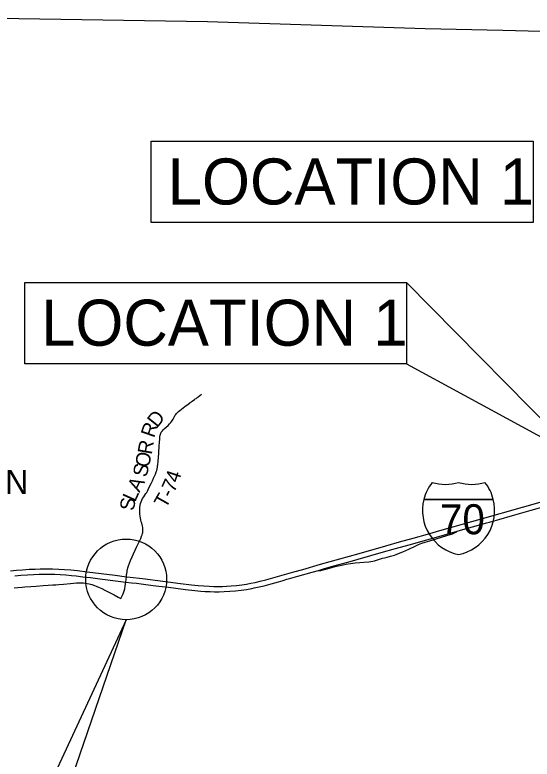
# Model space of a CAD drawing. Extents: x -29.6 to 34, y 0 to 22.
# Drawn here: x -16.109 to -14.201, y 3.352 to 6.1 of the extents above; entities that cross this region are included whole.
import ezdxf

# ---------------------------------------------------------------- set-up
doc = ezdxf.new("R2010")
doc.units = 0
for name, color, linetype in [('BR_P_Gen_Text', 7, 'Continuous'), ('Default', 7, 'Continuous'), ('GM_X_Corporation_Text', 7, 'Continuous'), ('GM_X_County_Road', 7, 'Continuous'), ('GM_X_Interchange_Ramps', 7, 'Continuous'), ('GM_X_Interstate_Route', 7, 'Continuous'), ('GM_X_Interstate_Shield', 7, 'Continuous'), ('GM_X_Township', 7, 'Continuous'), ('GM_X_Township_Road', 7, 'Continuous'), ('GM_X_Township_Road_Text', 7, 'Continuous'), ('GM_X_US_Route', 7, 'Continuous')]:
    doc.layers.add(name, color=color, linetype=linetype)

msp = doc.modelspace()

# ---------------------------------------------------------------- linework, layer by layer
at = {"layer": 'BR_P_Gen_Text'}
for points in [[(-15.6064, 5.6331), (-14.1976, 5.6331), (-14.1976, 5.3329), (-15.6064, 5.3329)], [(-16.0733, 5.1118), (-14.6646, 5.1118), (-14.6646, 4.8115), (-16.0733, 4.8115)], [(-14.6646, 5.1118), (-14.6646, 4.8115), (-14.027, 4.4641)], [(-16.0951, 3.013), (-16.0951, 2.7127), (-15.6989, 3.8667)]]:
    msp.add_lwpolyline(points, close=True, dxfattribs=at)
at = {"layer": 'Default'}
msp.add_circle((-15.6989, 4.0157), 0.149, dxfattribs=at)
at = {"layer": 'GM_X_County_Road'}
msp.add_lwpolyline([(-16.1119, 3.9847), (-16.0991, 3.9857), (-16.0829, 3.987), (-16.0724, 3.9879), (-16.0504, 3.9896), (-16.0313, 3.9909), (-16.0046, 3.9926), (-15.9861, 3.9941), (-15.9692, 3.9953), (-15.9582, 3.9961), (-15.9478, 3.9969), (-15.9304, 3.9984), (-15.9049, 4.0005), (-15.8817, 4.0025), (-15.8724, 4.0031), (-15.8648, 4.0031), (-15.856, 4.0026), (-15.8484, 4.0017), (-15.8432, 4.0009), (-15.8358, 3.9992), (-15.8251, 3.9963), (-15.8161, 3.9936), (-15.809, 3.991), (-15.8009, 3.9876), (-15.7893, 3.982), (-15.7773, 3.9761), (-15.7551, 3.9646), (-15.7433, 3.9583), (-15.7284, 3.9504), (-15.718, 3.9454)], dxfattribs=at)
at = {"layer": 'GM_X_Interchange_Ramps'}
msp.add_lwpolyline([(-14.9893, 4.0489), (-14.9877, 4.0487), (-14.986, 4.0486), (-14.9845, 4.0487), (-14.9827, 4.0488), (-14.9806, 4.0491), (-14.9766, 4.0499), (-14.958, 4.0547), (-14.9226, 4.0644), (-14.9096, 4.0676), (-14.8982, 4.0701), (-14.8879, 4.0721), (-14.8712, 4.0746), (-14.8544, 4.0767), (-14.8371, 4.0785), (-14.8225, 4.0797), (-14.8039, 4.081), (-14.7958, 4.0819), (-14.789, 4.0831), (-14.7822, 4.0848), (-14.7716, 4.0879), (-14.7532, 4.0936), (-14.7459, 4.0957), (-14.7357, 4.0982), (-14.7239, 4.1014), (-14.7094, 4.1057), (-14.7028, 4.1079), (-14.6946, 4.1109), (-14.6777, 4.1175), (-14.6676, 4.1219), (-14.6565, 4.1271), (-14.6329, 4.1385), (-14.6201, 4.1442), (-14.6077, 4.1492), (-14.5961, 4.1532), (-14.5789, 4.1586), (-14.5159, 4.1777), (-14.4953, 4.1842), (-14.4905, 4.186), (-14.4871, 4.1877), (-14.4819, 4.1906), (-14.4793, 4.1923), (-14.4778, 4.1938)], dxfattribs=at)
at = {"layer": 'GM_X_Interstate_Route'}
for points in [[(-16.1258, 4.0468), (-16.1032, 4.0494), (-16.0812, 4.0513), (-16.0568, 4.053), (-16.0341, 4.0541), (-16.0161, 4.0546), (-15.9934, 4.0548), (-15.9707, 4.0545), (-15.9474, 4.0538), (-15.9265, 4.0525), (-15.9033, 4.0506), (-15.8784, 4.048), (-15.8432, 4.0437), (-15.7397, 4.0309), (-15.6978, 4.0258), (-15.6842, 4.0241), (-15.6385, 4.0185), (-15.564, 4.0091), (-15.4986, 4.001), (-15.4576, 3.9959), (-15.4332, 3.9933), (-15.4123, 3.9915), (-15.3931, 3.9903), (-15.3756, 3.9897), (-15.3599, 3.9896), (-15.3441, 3.9899), (-15.3284, 3.9906), (-15.311, 3.9918), (-15.2924, 3.9936), (-15.2727, 3.996), (-15.2554, 3.9985), (-15.2393, 4.0014), (-15.2228, 4.0048), (-15.204, 4.0093), (-15.1837, 4.0145), (-15.1495, 4.024), (-15.1148, 4.0339), (-15.0806, 4.0436), (-15.0475, 4.0528), (-14.9825, 4.0714), (-14.839, 4.1119), (-14.7404, 4.14), (-14.69, 4.1543), (-14.6401, 4.1684), (-14.5868, 4.1833), (-14.533, 4.1987), (-14.4887, 4.211), (-14.4539, 4.2207), (-14.3929, 4.2381), (-14.2365, 4.2822), (-14.1452, 4.3082)], [(-14.4778, 4.1938), (-14.4652, 4.1974), (-14.3991, 4.2159), (-14.3694, 4.2244), (-14.3582, 4.2276), (-14.3246, 4.2371), (-14.2736, 4.2516), (-14.2047, 4.271), (-14.1402, 4.2893)], [(-14.9893, 4.0489), (-14.9669, 4.0554), (-14.9282, 4.0665), (-14.9047, 4.0731), (-14.8817, 4.0795), (-14.7578, 4.1145), (-14.7051, 4.1294), (-14.6547, 4.1437), (-14.5902, 4.162), (-14.5454, 4.1747), (-14.4778, 4.1938)], [(-16.1102, 4.0293), (-16.0876, 4.0314), (-16.0631, 4.0331), (-16.041, 4.0342), (-16.02, 4.0349), (-16.0014, 4.0351), (-15.9839, 4.0351), (-15.9623, 4.0346), (-15.9419, 4.0337), (-15.921, 4.0323), (-15.9012, 4.0306), (-15.8838, 4.0288), (-15.8584, 4.0258), (-15.83, 4.0224), (-15.7965, 4.0181), (-15.7283, 4.0095), (-15.7001, 4.0061), (-15.6798, 4.0036), (-15.6612, 4.0014), (-15.6433, 3.9992), (-15.6173, 3.9959), (-15.5896, 3.9925), (-15.5549, 3.9882), (-15.5427, 3.9867), (-15.4803, 3.9788), (-15.4456, 3.9749), (-15.423, 3.9727), (-15.4073, 3.9714), (-15.3893, 3.9705), (-15.3725, 3.97), (-15.3556, 3.97), (-15.337, 3.9706), (-15.3161, 3.972), (-15.2958, 3.9739), (-15.2745, 3.9763), (-15.2554, 3.979), (-15.2359, 3.9823), (-15.2262, 3.9841), (-15.2086, 3.9879), (-15.19, 3.9925), (-15.1641, 3.9993), (-15.1372, 4.0069), (-15.1198, 4.0119), (-15.1058, 4.016), (-15.0919, 4.02), (-15.0655, 4.0274), (-15.0122, 4.0422), (-14.9893, 4.0489)]]:
    msp.add_lwpolyline(points, dxfattribs=at)
at = {"layer": 'GM_X_Interstate_Shield'}
for p, q in [((-14.6007, 4.3112), (-14.3445, 4.3112)), ((-14.3445, 4.3112), (-14.6007, 4.3112)), ((-14.3445, 4.3112), (-14.6007, 4.3112))]:
    msp.add_line(p, q, dxfattribs=at)
for centre, start, end in [((-14.4393, 4.2704), 141.669, 165.8066), ((-14.5212, 4.5328), 253.0091, 286.9909), ((-14.424, 4.5328), 253.0091, 286.9909), ((-14.5059, 4.2704), 14.1934, 38.331), ((-14.4393, 4.2704), 165.8066, 258.463), ((-14.5059, 4.2704), 281.537, 14.1934)]:
    msp.add_arc(centre, 0.1665, start, end, dxfattribs=at)
at = {"layer": 'GM_X_Township'}
msp.add_lwpolyline([(-16.907, 6.0998), (-16.7922, 6.098), (-15.3983, 6.0749), (-14.5953, 6.0489), (-14.3095, 6.0432), (-13.3257, 6.0175), (-12.5552, 5.9919), (-12.2845, 5.982)], dxfattribs=at)
at = {"layer": 'GM_X_Township_Road'}
for points in [[(-15.6949, 4.0469), (-15.6924, 4.058), (-15.69, 4.0664), (-15.6867, 4.0757), (-15.6828, 4.086), (-15.6774, 4.0989), (-15.661, 4.1349), (-15.6565, 4.1444), (-15.6453, 4.1673), (-15.642, 4.1748), (-15.6398, 4.1808), (-15.6385, 4.1852), (-15.6377, 4.1892), (-15.6372, 4.1938), (-15.637, 4.1985), (-15.6372, 4.2031), (-15.6378, 4.2077), (-15.6389, 4.2128), (-15.6415, 4.2229), (-15.6425, 4.2263), (-15.6431, 4.2285), (-15.6451, 4.2362), (-15.6462, 4.2412), (-15.6475, 4.2491), (-15.6483, 4.2566), (-15.6488, 4.263), (-15.6489, 4.2688), (-15.6487, 4.2752), (-15.6481, 4.2816), (-15.6469, 4.2896), (-15.6455, 4.2964), (-15.6437, 4.3026), (-15.6412, 4.3084), (-15.6381, 4.3141), (-15.6338, 4.321), (-15.626, 4.3326), (-15.6232, 4.337), (-15.6215, 4.34), (-15.6203, 4.342), (-15.6177, 4.3472), (-15.6114, 4.3608), (-15.607, 4.3696), (-15.6021, 4.3795), (-15.5975, 4.3895), (-15.5912, 4.4039), (-15.5878, 4.4125), (-15.5862, 4.4175), (-15.5847, 4.4237), (-15.5834, 4.4306), (-15.5828, 4.4352), (-15.5824, 4.4386), (-15.5811, 4.4508), (-15.5798, 4.4665), (-15.5788, 4.481), (-15.5783, 4.4891), (-15.5781, 4.4926), (-15.578, 4.4949), (-15.5778, 4.4978), (-15.5771, 4.51), (-15.5768, 4.5129), (-15.5763, 4.5175), (-15.5761, 4.5198), (-15.5759, 4.5227), (-15.5758, 4.5239), (-15.5757, 4.525), (-15.5753, 4.5314), (-15.5743, 4.5424), (-15.5734, 4.5476), (-15.5724, 4.5516), (-15.571, 4.5554), (-15.5693, 4.5591), (-15.5675, 4.562), (-15.5653, 4.5648), (-15.5625, 4.5678), (-15.5587, 4.5713), (-15.5509, 4.5783), (-15.5445, 4.5842), (-15.5388, 4.5899), (-15.5342, 4.5952), (-15.531, 4.5993), (-15.5284, 4.6032), (-15.5258, 4.6077), (-15.5209, 4.6169), (-15.5188, 4.6205), (-15.5162, 4.6243), (-15.5129, 4.6284), (-15.5094, 4.6322), (-15.5059, 4.6354), (-15.5005, 4.6398), (-15.482, 4.6539), (-15.4708, 4.6622), (-15.4647, 4.6667), (-15.4624, 4.6683), (-15.461, 4.6694), (-15.46, 4.67), (-15.4577, 4.6717), (-15.4554, 4.6735), (-15.4466, 4.68), (-15.4438, 4.6821), (-15.441, 4.6841), (-15.4387, 4.6858), (-15.4363, 4.6875), (-15.4331, 4.6899), (-15.4269, 4.6948), (-15.4206, 4.6997)], [(-15.718, 3.9454), (-15.7109, 3.9602), (-15.7084, 3.9667), (-15.7063, 3.9733), (-15.7043, 3.9812), (-15.7024, 3.9903), (-15.7009, 3.9995), (-15.7001, 4.0061), (-15.6989, 4.0157), (-15.6978, 4.0258), (-15.6972, 4.0319), (-15.6954, 4.044), (-15.6949, 4.0469)]]:
    msp.add_lwpolyline(points, dxfattribs=at)
at = {"layer": 'GM_X_US_Route'}
for points in [[(-14.4778, 4.1938), (-14.4652, 4.1974), (-14.3991, 4.2159), (-14.3694, 4.2244), (-14.3582, 4.2276), (-14.3246, 4.2371), (-14.2736, 4.2516), (-14.2047, 4.271), (-14.1402, 4.2893)], [(-14.9893, 4.0489), (-14.9669, 4.0554), (-14.9282, 4.0665), (-14.9047, 4.0731), (-14.8817, 4.0795), (-14.7578, 4.1145), (-14.7051, 4.1294), (-14.6547, 4.1437), (-14.5902, 4.162), (-14.5454, 4.1747), (-14.4778, 4.1938)], [(-16.1102, 4.0293), (-16.0876, 4.0314), (-16.0631, 4.0331), (-16.041, 4.0342), (-16.02, 4.0349), (-16.0014, 4.0351), (-15.9839, 4.0351), (-15.9623, 4.0346), (-15.9419, 4.0337), (-15.921, 4.0323), (-15.9012, 4.0306), (-15.8838, 4.0288), (-15.8584, 4.0258), (-15.83, 4.0224), (-15.7965, 4.0181), (-15.7283, 4.0095), (-15.7001, 4.0061), (-15.6798, 4.0036), (-15.6612, 4.0014), (-15.6433, 3.9992), (-15.6173, 3.9959), (-15.5896, 3.9925), (-15.5549, 3.9882), (-15.5427, 3.9867), (-15.4803, 3.9788), (-15.4456, 3.9749), (-15.423, 3.9727), (-15.4073, 3.9714), (-15.3893, 3.9705), (-15.3725, 3.97), (-15.3556, 3.97), (-15.337, 3.9706), (-15.3161, 3.972), (-15.2958, 3.9739), (-15.2745, 3.9763), (-15.2554, 3.979), (-15.2359, 3.9823), (-15.2262, 3.9841), (-15.2086, 3.9879), (-15.19, 3.9925), (-15.1641, 3.9993), (-15.1372, 4.0069), (-15.1198, 4.0119), (-15.1058, 4.016), (-15.0919, 4.02), (-15.0655, 4.0274), (-15.0122, 4.0422), (-14.9893, 4.0489)]]:
    msp.add_lwpolyline(points, dxfattribs=at)

# ---------------------------------------------------------------- texts
at = {"layer": 'BR_P_Gen_Text'}
for p in [(-15.5456, 5.3997), (-16.0126, 4.8784)]:
    msp.add_text('LOCATION 1', height=0.17, dxfattribs=at).set_placement(p)
at = {"layer": 'GM_X_Corporation_Text'}
msp.add_text('OLD WASHINGTON', height=0.088778, rotation=0, dxfattribs=at).set_placement((-17.1544, 4.3311))
at = {"layer": 'GM_X_Interstate_Shield'}
msp.add_text('70', height=0.11097, dxfattribs=at).set_placement((-14.5408, 4.1822))
at = {"layer": 'GM_X_Township_Road_Text'}
for s, rotation, p in [('D', 51.4557, (-15.5844, 4.5731)), ('R', 71.0059, (-15.5964, 4.5359)), ('R', 80.3752, (-15.6048, 4.4746)), ('O', 77.2997, (-15.6158, 4.4258)), ('S', 78.0136, (-15.6232, 4.3909)), ('4', 71.4348, (-15.5062, 4.3695)), ('A', 62.5031, (-15.6501, 4.3345)), ('7', 65.4647, (-15.522, 4.334)), ('-', 65.4855, (-15.5311, 4.3141)), ('S', 81.8047, (-15.6702, 4.2671)), ('L', 65.7316, (-15.6662, 4.2989)), ('T', 60.6203, (-15.5529, 4.275))]:
    msp.add_text(s, height=0.0533, rotation=rotation, dxfattribs=at).set_placement(p)

doc.saveas('drawing.dxf')
